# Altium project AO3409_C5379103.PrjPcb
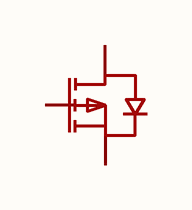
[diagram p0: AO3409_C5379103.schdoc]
1 sheet, 1 parts. Net scope: global (net labels, ports and power ports of the same name join across sheets).

## Sheet AO3409_C5379103.schdoc
size 127 x 101 mm

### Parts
Q?  ao3409_c5379103  [SOT-23-3_L2.9-W1.6-P1.90-LS2.8-BR]  (value not drawn)

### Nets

Not connected (* = marked no-connect by the designer): Q? 1(G) 2(S) 3(D)

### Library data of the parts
Q? = ao3409_c5379103: 数量:1个P沟道;漏源电压(Vdss):30V;连续漏极电流(Id):3A;导通电阻(RDS(on)):75mΩ@10V;耗散功率(Pd):1.56W;阈值电压(Vgs(th)):1.6V;; Manufacturer: MSKSEMI(美森科); ManufacturerPart: AO3409; AddInBom: yes; ModelId: 89cb27a44ab2466697082bb9fd73a7d0; ModelName: SOT-23-3L_L2.9-W1.6-H1.1-LS2.8-P0.95; ModelTransform: 114.173,110.236,0,90,0,0,0,0,0; Number: 1个P沟道; Drain to Source Voltage: 30V; Current - Continuous Drain(Id): 3A; Pd - Power Dissipation: 1.56W; Gate Threshold Voltage (Vgs(th)): 1.6V; Gate Charge(Qg): 2.5nC@4.5V; Input Capacitance(Ciss): 226pF; Reverse Transfer Capacitance (Crss@Vds): 29pF; Output Capacitance(Coss): 39pF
